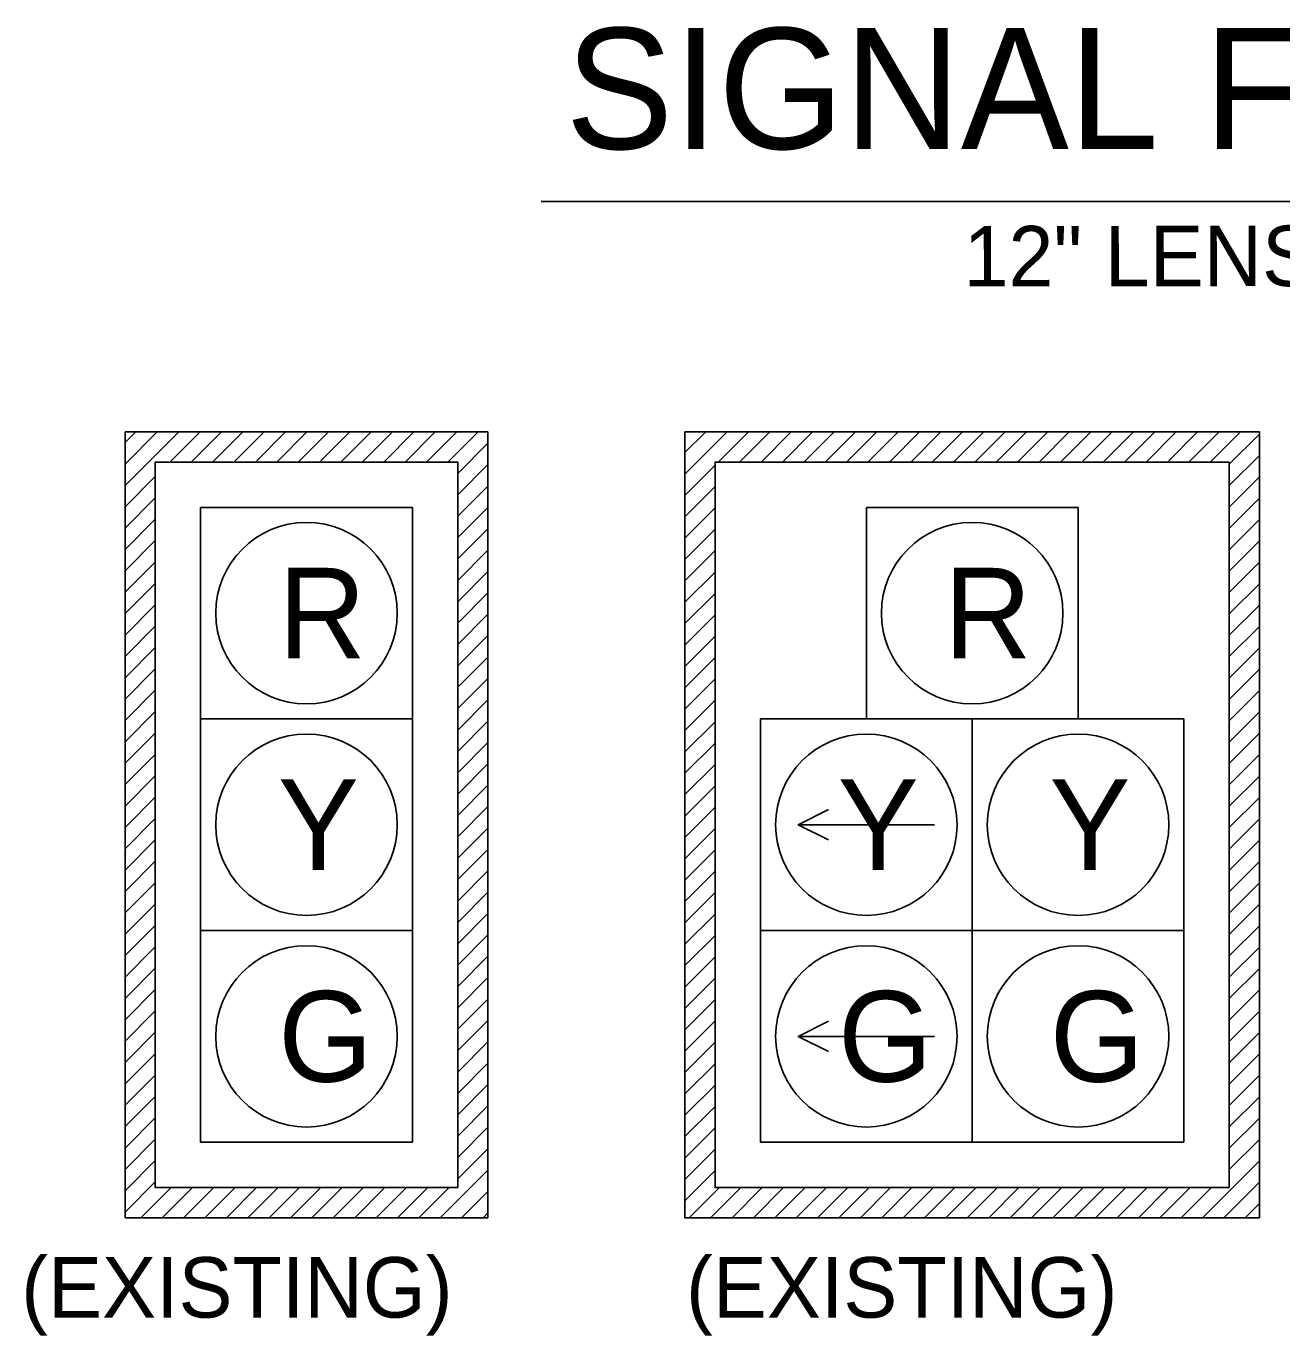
# Model space of a CAD drawing. Extents: x 110 to 419214, y -565865 to 630.
# Drawn here: x 296.4 to 379.5, y 357 to 443.6 of the extents above; entities that cross this region are included whole.
import ezdxf

# ---------------------------------------------------------------- set-up
doc = ezdxf.new("R2010")
doc.units = 0
doc.layers.add('T_Drafting', color=7, linetype='Continuous')
doc.layers.add('T_Notes', color=7, linetype='Continuous')

msp = doc.modelspace()

# ---------------------------------------------------------------- linework, layer by layer
at = {"layer": 'T_Drafting'}
for p, q in [((326.965, 416.766), (302.965, 416.766)), ((302.965, 416.766), (302.965, 364.766)), ((302.965, 413.219), (306.512, 416.766)), ((302.965, 414.633), (305.098, 416.766)), ((302.965, 416.048), (303.684, 416.766)), ((305.926, 414.766), (307.926, 416.766)), ((307.341, 414.766), (309.341, 416.766)), ((308.755, 414.766), (310.755, 416.766)), ((310.169, 414.766), (312.169, 416.766)), ((311.583, 414.766), (313.583, 416.766)), ((312.997, 414.766), (314.997, 416.766)), ((314.412, 414.766), (316.412, 416.766)), ((315.826, 414.766), (317.826, 416.766)), ((317.24, 414.766), (319.24, 416.766)), ((318.654, 414.766), (320.654, 416.766)), ((320.069, 414.766), (322.069, 416.766)), ((321.483, 414.766), (323.483, 416.766)), ((322.897, 414.766), (324.897, 416.766)), ((324.311, 414.766), (326.311, 416.766)), ((326.965, 364.766), (326.965, 416.766)), ((377.983, 416.766), (339.983, 416.766)), ((339.983, 416.766), (339.983, 364.766)), ((339.983, 413.972), (342.776, 416.766)), ((339.983, 415.386), (341.362, 416.766)), ((342.19, 414.766), (344.19, 416.766)), ((343.605, 414.766), (345.605, 416.766)), ((345.019, 414.766), (347.019, 416.766)), ((346.433, 414.766), (348.433, 416.766)), ((347.847, 414.766), (349.847, 416.766)), ((349.261, 414.766), (351.261, 416.766)), ((350.676, 414.766), (352.676, 416.766)), ((352.09, 414.766), (354.09, 416.766)), ((353.504, 414.766), (355.504, 416.766)), ((354.918, 414.766), (356.918, 416.766)), ((356.332, 414.766), (358.332, 416.766)), ((357.747, 414.766), (359.747, 416.766)), ((359.161, 414.766), (361.161, 416.766)), ((360.575, 414.766), (362.575, 416.766)), ((361.989, 414.766), (363.989, 416.766)), ((363.404, 414.766), (365.404, 416.766)), ((364.818, 414.766), (366.818, 416.766)), ((366.232, 414.766), (368.232, 416.766)), ((367.646, 414.766), (369.646, 416.766)), ((369.06, 414.766), (371.06, 416.766)), ((370.475, 414.766), (372.475, 416.766)), ((371.889, 414.766), (373.889, 416.766)), ((373.303, 414.766), (375.303, 416.766)), ((374.717, 414.766), (376.717, 416.766)), ((377.983, 364.766), (377.983, 416.766)), ((324.965, 414.006), (326.965, 416.006)), ((375.983, 414.617), (377.983, 416.617)), ((375.983, 413.203), (377.983, 415.203)), ((324.965, 412.592), (326.965, 414.592)), ((339.983, 412.558), (341.983, 414.558)), ((302.965, 411.805), (304.965, 413.805)), ((375.983, 411.788), (377.983, 413.788)), ((324.965, 411.177), (326.965, 413.177)), ((339.983, 411.144), (341.983, 413.144)), ((302.965, 410.391), (304.965, 412.391)), ((307.965, 411.766), (321.965, 411.766)), ((307.965, 411.766), (307.965, 397.766)), ((321.965, 411.766), (321.965, 397.766)), ((324.965, 409.763), (326.965, 411.763)), ((339.983, 409.73), (341.983, 411.73)), ((351.983, 411.766), (365.983, 411.766)), ((351.983, 411.766), (351.983, 397.766)), ((365.983, 411.766), (365.983, 397.766)), ((375.983, 410.374), (377.983, 412.374)), ((302.965, 408.976), (304.965, 410.976)), ((375.983, 408.96), (377.983, 410.96)), ((324.965, 408.349), (326.965, 410.349)), ((339.983, 408.315), (341.983, 410.315)), ((302.965, 407.562), (304.965, 409.562)), ((375.983, 407.546), (377.983, 409.546)), ((302.965, 406.148), (304.965, 408.148)), ((324.965, 406.935), (326.965, 408.935)), ((339.983, 406.901), (341.983, 408.901)), ((375.983, 406.132), (377.983, 408.132)), ((324.965, 405.521), (326.965, 407.521)), ((339.983, 405.487), (341.983, 407.487)), ((302.965, 404.734), (304.965, 406.734)), ((375.983, 404.717), (377.983, 406.717)), ((324.965, 404.106), (326.965, 406.106)), ((339.983, 404.073), (341.983, 406.073)), ((302.965, 403.32), (304.965, 405.32)), ((324.965, 402.692), (326.965, 404.692)), ((339.983, 402.659), (341.983, 404.659)), ((375.983, 403.303), (377.983, 405.303)), ((302.965, 401.905), (304.965, 403.905)), ((375.983, 401.889), (377.983, 403.889)), ((324.965, 401.278), (326.965, 403.278)), ((339.983, 401.244), (341.983, 403.244)), ((302.965, 400.491), (304.965, 402.491)), ((375.983, 400.475), (377.983, 402.475)), ((324.965, 399.864), (326.965, 401.864)), ((339.983, 399.83), (341.983, 401.83)), ((302.965, 399.077), (304.965, 401.077)), ((324.965, 398.45), (326.965, 400.45)), ((339.983, 398.416), (341.983, 400.416)), ((375.983, 399.061), (377.983, 401.061)), ((302.965, 397.663), (304.965, 399.663)), ((375.983, 397.646), (377.983, 399.646)), ((324.965, 397.035), (326.965, 399.035)), ((339.983, 397.002), (341.983, 399.002)), ((302.965, 396.249), (304.965, 398.249)), ((307.965, 397.766), (321.965, 397.766)), ((307.965, 397.766), (307.965, 383.766)), ((321.965, 397.766), (321.965, 383.766)), ((344.983, 397.766), (344.983, 383.766)), ((344.983, 397.766), (358.983, 397.766)), ((358.983, 397.766), (358.983, 383.766)), ((358.983, 397.766), (372.983, 397.766)), ((358.983, 397.766), (358.983, 383.766)), ((372.983, 397.766), (372.983, 383.766)), ((375.983, 396.232), (377.983, 398.232)), ((302.965, 394.834), (304.965, 396.834)), ((324.965, 395.621), (326.965, 397.621)), ((339.983, 395.587), (341.983, 397.587)), ((324.965, 394.207), (326.965, 396.207)), ((339.983, 394.173), (341.983, 396.173)), ((375.983, 394.818), (377.983, 396.818)), ((302.965, 393.42), (304.965, 395.42)), ((375.983, 393.404), (377.983, 395.404)), ((324.965, 392.793), (326.965, 394.793)), ((339.983, 392.759), (341.983, 394.759)), ((302.965, 392.006), (304.965, 394.006)), ((324.965, 391.378), (326.965, 393.378)), ((375.983, 391.989), (377.983, 393.989)), ((302.965, 390.592), (304.965, 392.592)), ((339.983, 391.345), (341.983, 393.345)), ((375.983, 390.575), (377.983, 392.575)), ((324.965, 389.964), (326.965, 391.964)), ((339.983, 389.931), (341.983, 391.931)), ((302.965, 389.177), (304.965, 391.177)), ((356.483, 390.766), (347.483, 390.766)), ((375.983, 389.161), (377.983, 391.161)), ((324.965, 388.55), (326.965, 390.55)), ((339.983, 388.516), (341.983, 390.516)), ((302.965, 387.763), (304.965, 389.763)), ((324.965, 387.136), (326.965, 389.136)), ((339.983, 387.102), (341.983, 389.102)), ((375.983, 387.747), (377.983, 389.747)), ((302.965, 386.349), (304.965, 388.349)), ((375.983, 386.333), (377.983, 388.333)), ((324.965, 385.722), (326.965, 387.722)), ((339.983, 385.688), (341.983, 387.688)), ((302.965, 384.935), (304.965, 386.935)), ((375.983, 384.918), (377.983, 386.918)), ((324.965, 384.307), (326.965, 386.307)), ((339.983, 384.274), (341.983, 386.274)), ((302.965, 383.521), (304.965, 385.521)), ((324.965, 382.893), (326.965, 384.893)), ((339.983, 382.86), (341.983, 384.86)), ((375.983, 383.504), (377.983, 385.504)), ((302.965, 382.106), (304.965, 384.106)), ((375.983, 382.09), (377.983, 384.09)), ((307.965, 383.766), (321.965, 383.766)), ((307.965, 383.766), (307.965, 369.766)), ((321.965, 383.766), (321.965, 369.766)), ((324.965, 381.479), (326.965, 383.479)), ((339.983, 381.445), (341.983, 383.445)), ((344.983, 383.766), (358.983, 383.766)), ((344.983, 383.766), (344.983, 369.766)), ((358.983, 383.766), (358.983, 369.766)), ((358.983, 383.766), (372.983, 383.766)), ((358.983, 383.766), (358.983, 369.766)), ((372.983, 383.766), (372.983, 369.766)), ((302.965, 380.692), (304.965, 382.692)), ((375.983, 380.676), (377.983, 382.676)), ((302.965, 379.278), (304.965, 381.278)), ((324.965, 380.065), (326.965, 382.065)), ((339.983, 380.031), (341.983, 382.031)), ((375.983, 379.262), (377.983, 381.262)), ((324.965, 378.651), (326.965, 380.651)), ((339.983, 378.617), (341.983, 380.617)), ((302.965, 377.864), (304.965, 379.864)), ((375.983, 377.847), (377.983, 379.847)), ((324.965, 377.236), (326.965, 379.236)), ((339.983, 377.203), (341.983, 379.203)), ((302.965, 376.45), (304.965, 378.45)), ((324.965, 375.822), (326.965, 377.822)), ((339.983, 375.788), (341.983, 377.788)), ((375.983, 376.433), (377.983, 378.433)), ((302.965, 375.035), (304.965, 377.035)), ((375.983, 375.019), (377.983, 377.019)), ((324.965, 374.408), (326.965, 376.408)), ((339.983, 374.374), (341.983, 376.374)), ((356.483, 376.766), (347.483, 376.766)), ((302.965, 373.621), (304.965, 375.621)), ((375.983, 373.605), (377.983, 375.605)), ((324.965, 372.994), (326.965, 374.994)), ((339.983, 372.96), (341.983, 374.96)), ((302.965, 372.207), (304.965, 374.207)), ((324.965, 371.579), (326.965, 373.579)), ((339.983, 371.546), (341.983, 373.546)), ((375.983, 372.19), (377.983, 374.19)), ((302.965, 370.793), (304.965, 372.793)), ((375.983, 370.776), (377.983, 372.776)), ((324.965, 370.165), (326.965, 372.165)), ((339.983, 370.132), (341.983, 372.132)), ((302.965, 369.378), (304.965, 371.378)), ((375.983, 369.362), (377.983, 371.362)), ((324.965, 368.751), (326.965, 370.751)), ((339.983, 368.717), (341.983, 370.717)), ((302.965, 367.964), (304.965, 369.964)), ((307.965, 369.766), (321.965, 369.766)), ((324.965, 367.337), (326.965, 369.337)), ((339.983, 367.303), (341.983, 369.303)), ((344.983, 369.766), (358.983, 369.766)), ((358.983, 369.766), (372.983, 369.766)), ((375.983, 367.948), (377.983, 369.948)), ((302.965, 366.55), (304.965, 368.55)), ((374.215, 364.766), (377.983, 368.534)), ((323.809, 364.766), (326.965, 367.923)), ((339.983, 365.889), (341.983, 367.889)), ((302.965, 365.136), (304.965, 367.136)), ((304.01, 364.766), (306.01, 366.766)), ((305.424, 364.766), (307.424, 366.766)), ((306.838, 364.766), (308.838, 366.766)), ((308.252, 364.766), (310.252, 366.766)), ((309.667, 364.766), (311.667, 366.766)), ((311.081, 364.766), (313.081, 366.766)), ((312.495, 364.766), (314.495, 366.766)), ((313.909, 364.766), (315.909, 366.766)), ((315.323, 364.766), (317.323, 366.766)), ((316.738, 364.766), (318.738, 366.766)), ((318.152, 364.766), (320.152, 366.766)), ((319.566, 364.766), (321.566, 366.766)), ((320.98, 364.766), (322.98, 366.766)), ((322.394, 364.766), (324.394, 366.766)), ((325.223, 364.766), (326.965, 366.508)), ((340.274, 364.766), (342.274, 366.766)), ((341.688, 364.766), (343.688, 366.766)), ((343.102, 364.766), (345.102, 366.766)), ((344.516, 364.766), (346.516, 366.766)), ((345.93, 364.766), (347.93, 366.766)), ((347.345, 364.766), (349.345, 366.766)), ((348.759, 364.766), (350.759, 366.766)), ((350.173, 364.766), (352.173, 366.766)), ((351.587, 364.766), (353.587, 366.766)), ((353.002, 364.766), (355.002, 366.766)), ((354.416, 364.766), (356.416, 366.766)), ((355.83, 364.766), (357.83, 366.766)), ((357.244, 364.766), (359.244, 366.766)), ((358.658, 364.766), (360.658, 366.766)), ((360.073, 364.766), (362.073, 366.766)), ((361.487, 364.766), (363.487, 366.766)), ((362.901, 364.766), (364.901, 366.766)), ((364.315, 364.766), (366.315, 366.766)), ((365.729, 364.766), (367.729, 366.766)), ((367.144, 364.766), (369.144, 366.766)), ((368.558, 364.766), (370.558, 366.766)), ((369.972, 364.766), (371.972, 366.766)), ((371.386, 364.766), (373.386, 366.766)), ((372.801, 364.766), (374.801, 366.766)), ((375.629, 364.766), (377.983, 367.119)), ((377.043, 364.766), (377.983, 365.705)), ((326.637, 364.766), (326.965, 365.094)), ((302.965, 364.766), (326.965, 364.766)), ((339.983, 364.766), (377.983, 364.766))]:
    msp.add_line(p, q, dxfattribs=at)
for points in [[(324.965, 366.766), (324.965, 414.766), (304.965, 414.766), (304.965, 366.766)], [(375.983, 414.766), (341.983, 414.766), (341.983, 366.766), (375.983, 366.766)]]:
    msp.add_lwpolyline(points, close=True, dxfattribs=at)
for points in [[(349.483, 391.766), (347.483, 390.766), (349.483, 389.766)], [(349.483, 377.766), (347.483, 376.766), (349.483, 375.766)]]:
    msp.add_lwpolyline(points, dxfattribs=at)
for centre in [(314.965, 404.766), (358.983, 404.766), (314.965, 390.766), (351.983, 390.766), (365.983, 390.766), (314.965, 376.766), (351.983, 376.766), (365.983, 376.766)]:
    msp.add_circle(centre, 6, dxfattribs=at)
at = {"layer": 'T_Notes'}
msp.add_line((330.484, 432.011), (428.669, 432.011), dxfattribs=at)

# ---------------------------------------------------------------- texts
at = {"layer": 'T_Drafting'}
for s, height, rotation, p in [('12" LENSES', 4, 0.07203, (358.41, 426.377)), ('R', 5.998, 360, (313.1, 401.767)), ('R', 5.998, 360, (357.117, 401.767)), ('Y', 5.998, 360, (313.076, 387.767)), ('Y', 5.998, 360, (350.094, 387.767)), ('Y', 5.998, 360, (364.094, 387.767)), ('G', 5.998, 360, (313.099, 373.767)), ('G', 5.998, 360, (350.116, 373.767)), ('G', 5.998, 360, (364.116, 373.767))]:
    msp.add_text(s, height=height, rotation=rotation, dxfattribs=at).set_placement(p)
at = {"layer": 'T_Notes'}
for s, height, p in [('SIGNAL FACES', 8, (332.083, 435.48)), ('(EXISTING)', 4, (296.099, 358.16)), ('(EXISTING)', 4, (340.059, 358.16))]:
    msp.add_text(s, height=height, rotation=360, dxfattribs=at).set_placement(p)

doc.saveas('drawing.dxf')
